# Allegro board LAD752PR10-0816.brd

Outline 338.42 x 185.75 mm; copper layers: TOP, GND1, IN1, GND2, IN2, VCC, GND3, IN3, GND4, IN4, GND5, BOTTOM. Coordinates in mm from the lower left corner of the outline.

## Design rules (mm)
net group B+: nets CPU_B+ GPU_B+
net group CLK_PCIE_6: nets CLK_PCIE_N6 CLK_PCIE_P6
net group CLK_PCIE_7: nets CLK_PCIE_N7 CLK_PCIE_P7
net group CPU_EDP_TX2P: nets CPU_EDP_TX2N CPU_EDP_TX2P
net group DDR-ALERT: nets DDR_A_ALERT# DDR_B_ALERT#
net group DDR-RST: nets DDR4_DRAMRST# H_DRAMRST#
net group DDRB-CLK: nets M_CLK_DDR2 M_CLK_DDR#2
net group DIFFPAIR29: nets FBB_CLK0 FBB_CLK0#
net group DIFFPAIR36: nets FBB_WCK3 FBB_WCK3_N
net group DIFFPAIR38: nets FBB_WCK1 FBB_WCK1_N
net group DIFFPAIR50: nets M_CLK_DDR3 M_CLK_DDR#3
net group DIFFPAIR70: nets CSSN_1 CSSP_1
net group DIFFPAIR85: nets TP_CLK TP_DATA
net group DIFFPAIR148: nets REMOTE3+ REMOTE3-
net group DIFFPAIR152: nets TBTA_I2C_SCL1_R TBTA_I2C_SDA1_R
net group DIFFPAIR156: nets CPU_DDC1CLK CPU_DDC1DATA
net group DIFFPAIR157: nets CPU_DDC2CLK CPU_DDC2DATA
net group DIFFPAIR164: nets N39112837 N39112883
net group DIFFPAIR165: nets N39112974 N39113020
net group DIFFPAIR166: nets N39113066 N39113112
net group DIFFPAIR167: nets N39113201 N39113246
net group DIFFPAIR168: nets PCIE_PTX_DRX_N13_C PCIE_PTX_DRX_P13_C
net group DIFFPAIR169: nets PCIE_PTX_DRX_N12_C PCIE_PTX_DRX_P12_C
net group DIFFPAIR170: nets PCIE_PTX_DRX_N11_C PCIE_PTX_DRX_P11_C
net group DIFFPAIR171: nets PCIE_PTX_DRX_N10_C PCIE_PTX_DRX_P10_C
net group DIFFPAIR172: nets PCIE_PTX_DRX_N9_C PCIE_PTX_DRX_P9_C
net group DIFFPAIR173: nets PCIE_PTX_DRX_N14_C PCIE_PTX_DRX_P14_C
net group DIFFPAIR174: nets PCIE_PTX_DRX_N18_C PCIE_PTX_DRX_P18_C
net group DIFFPAIR175: nets PCIE_PTX_DRX_N19_C PCIE_PTX_DRX_P19_C
net group DIFFPAIR176: nets PCIE_PTX_DRX_N20_C PCIE_PTX_DRX_P20_C
net group DIFFPAIR177: nets PCIE_PTX_DRX_N17_C PCIE_PTX_DRX_P17_C
net group DP18: nets FBA_CLK1 FBA_CLK1#
net group FBA-CLK: nets FBA_CLK0 FBA_CLK0#
net group FBB-CLK: nets FBB_CLK1 FBB_CLK1#
net group FBC-CLK: nets FBC_CLK0 FBC_CLK0#
net group FBC_CLK1: nets FBC_CLK1 FBC_CLK1#
net group FBC_WCK0: nets FBC_WCK0 FBC_WCK0_N
net group FBC_WCK2: nets FBC_WCK2 FBC_WCK2_N
net group SW_USB20_1: nets SW_USB20_N1 SW_USB20_P1
net group USB3_CRX_L_DTX_2: nets USB3_CRX_L_DTX_N2 USB3_CRX_L_DTX_P2
net group USB3_CRX_L_DTX_5: nets USB3_CRX_L_DTX_N5 USB3_CRX_L_DTX_P5
net group USB3_CTX_C_DRX_2: nets USB3_CTX_C_DRX_N2 USB3_CTX_C_DRX_P2
net group USB3_CTX_C_DRX_5: nets USB3_CTX_C_DRX_N5 USB3_CTX_C_DRX_P5
net group USB3_CTX_C_L_DRX_2: nets USB3_CTX_C_L_DRX_N2 USB3_CTX_C_L_DRX_P2
net group USB3_CTX_C_L_DRX_5: nets USB3_CTX_C_L_DRX_N5 USB3_CTX_C_L_DRX_P5
net group USB3R2: nets USB3RN2 USB3RP2
net group USB3T2: nets USB3TN2 USB3TP2
net group USB20_8_CONN: nets USB20_N8_CONN USB20_P8_CONN
net group VGA_SMB: nets VGA_SMB_CK3 VGA_SMB_DA3
net group 12: nets CFG0 CFG1 CFG2 CFG3 CFG4 CFG5 CFG6 CFG7 CFG8 CFG9 CFG10 CFG11 CFG12 CFG13 CFG14 CFG15 CFG16 CFG17 CFG18 CFG19
net group 13.5/12: nets GPU_MDP_N0 GPU_MDP_N1 GPU_MDP_N2 GPU_MDP_N3 GPU_MDP_P0 GPU_MDP_P1 GPU_MDP_P2 GPU_MDP_P3
net group 15: nets IN1_PEQ# IN2_PEQ# PEG_RCOMP
net group 25: nets EDP_RCOMP
net group ASYNCHRONOUS: nets CALDERA_RST# CDRA_RST# CPU_TRIGGER DGPU_HOLD_RST# DGPU_PEX_RST# DGPU_PWROK H_CPUPWRGD H_PECI H_PM_DOWN H_PM_SYNC_R H_PROCHOT# H_THERMTRIP# H_THERMTRIP#_R H_VCCST_PWRGD PCH_DPWROK PCH_PECI PCH_PLTRST# PCH_PWROK PCH_TRIGGER PCIECOMP PCIECOMP# PECI_KB9012 PLTRST_CPU# SYS_PWROK USB2_COMP VCCIO_PGOOD VR_HOT#
net group CODEC: nets HP2_D_L_C HP2_D_L_R HP2_D_R_C HP2_D_R_R HPOUT-L HPOUT-R
net group CRITICAL LOW SPEED: nets INTRUDER# PBTN_OUT# PCH_RTCRST# PCH_SRTCRST# PCIE_WAKE#
net group CRYSTAL: nets PCH_RTCX1 PCH_RTCX2 TBT_XTAL_25_IN TBT_XTAL_25_OUT XTAL24_IN XTAL24_OUT XTAL_OUT XTALIN XTLI XTLO
net group DDR-RCOMP: nets DDR_RCOMP0 DDR_RCOMP1 DDR_RCOMP2
net group DDRA-CLK: nets M_CLK_DDR0 M_CLK_DDR1 M_CLK_DDR#0 M_CLK_DDR#1
net group DDRA-CMD: nets DDR_A_BG0 DDR_A_BG1 DDR_A_BS0 DDR_A_BS1 DDR_A_CAS# DDR_A_MA0 DDR_A_MA1 DDR_A_MA2 DDR_A_MA3 DDR_A_MA4 DDR_A_MA5 DDR_A_MA6 DDR_A_MA7 DDR_A_MA8 DDR_A_MA9 DDR_A_MA10 DDR_A_MA11 DDR_A_MA12 DDR_A_MA13 DDR_A_RAS# DDR_A_WE#
net group DDRA-CTL: nets DDR_A_ACT# DDR_A_PAR DDR_CKE0_DIMMA DDR_CKE1_DIMMA DDR_CS0_DIMMA# DDR_CS1_DIMMA#
net group DDRA-D0: nets DDR_A_D0 DDR_A_D1 DDR_A_D2 DDR_A_D3 DDR_A_D4 DDR_A_D5 DDR_A_D6 DDR_A_D7
net group DDRA-D1: nets DDR_A_D8 DDR_A_D9 DDR_A_D10 DDR_A_D11 DDR_A_D12 DDR_A_D13 DDR_A_D14 DDR_A_D15
net group DDRA-D2: nets DDR_A_D16 DDR_A_D17 DDR_A_D18 DDR_A_D19 DDR_A_D20 DDR_A_D21 DDR_A_D22 DDR_A_D23
net group DDRA-D3: nets DDR_A_D24 DDR_A_D25 DDR_A_D26 DDR_A_D27 DDR_A_D28 DDR_A_D29 DDR_A_D30 DDR_A_D31
net group DDRA-D4: nets DDR_A_D32 DDR_A_D33 DDR_A_D34 DDR_A_D35 DDR_A_D36 DDR_A_D37 DDR_A_D38 DDR_A_D39
net group DDRA-D5: nets DDR_A_D40 DDR_A_D41 DDR_A_D42 DDR_A_D43 DDR_A_D44 DDR_A_D45 DDR_A_D46 DDR_A_D47
net group DDRA-D6: nets DDR_A_D48 DDR_A_D49 DDR_A_D50 DDR_A_D51 DDR_A_D52 DDR_A_D53 DDR_A_D54 DDR_A_D55
net group DDRA-D7: nets DDR_A_D56 DDR_A_D57 DDR_A_D58 DDR_A_D59 DDR_A_D60 DDR_A_D61 DDR_A_D62 DDR_A_D63
net group DDRA-DQS: nets DDR_A_DQS0 DDR_A_DQS1 DDR_A_DQS2 DDR_A_DQS3 DDR_A_DQS4 DDR_A_DQS5 DDR_A_DQS6 DDR_A_DQS7 DDR_A_DQS#0 DDR_A_DQS#1 DDR_A_DQS#2 DDR_A_DQS#3 DDR_A_DQS#4 DDR_A_DQS#5 DDR_A_DQS#6 DDR_A_DQS#7
net group DDRB-CMD: nets DDR_B_BG0 DDR_B_BG1 DDR_B_BS0 DDR_B_BS1 DDR_B_CAS# DDR_B_MA0 DDR_B_MA1 DDR_B_MA2 DDR_B_MA3 DDR_B_MA4 DDR_B_MA5 DDR_B_MA6 DDR_B_MA7 DDR_B_MA8 DDR_B_MA9 DDR_B_MA10 DDR_B_MA11 DDR_B_MA12 DDR_B_MA13 DDR_B_RAS# DDR_B_WE#
net group DDRB-CTL: nets DDR_B_ACT# DDR_B_PAR DDR_CKE2_DIMMB DDR_CKE3_DIMMB DDR_CS2_DIMMB# DDR_CS3_DIMMB# M_ODT0 M_ODT1 M_ODT2 M_ODT3
net group DDRB-D0: nets DDR_B_D0 DDR_B_D1 DDR_B_D2 DDR_B_D3 DDR_B_D4 DDR_B_D5 DDR_B_D6 DDR_B_D7
net group DDRB-D1: nets DDR_B_D8 DDR_B_D9 DDR_B_D10 DDR_B_D11 DDR_B_D12 DDR_B_D13 DDR_B_D14 DDR_B_D15
net group DDRB-D2: nets DDR_B_D16 DDR_B_D17 DDR_B_D18 DDR_B_D19 DDR_B_D20 DDR_B_D21 DDR_B_D22 DDR_B_D23
net group DDRB-D3: nets DDR_B_D24 DDR_B_D25 DDR_B_D26 DDR_B_D27 DDR_B_D28 DDR_B_D29 DDR_B_D30 DDR_B_D31
net group DDRB-D4: nets DDR_B_D32 DDR_B_D33 DDR_B_D34 DDR_B_D35 DDR_B_D36 DDR_B_D37 DDR_B_D38 DDR_B_D39
net group DDRB-D5: nets DDR_B_D40 DDR_B_D41 DDR_B_D42 DDR_B_D43 DDR_B_D44 DDR_B_D45 DDR_B_D46 DDR_B_D47
net group DDRB-D6: nets DDR_B_D48 DDR_B_D49 DDR_B_D50 DDR_B_D51 DDR_B_D52 DDR_B_D53 DDR_B_D54 DDR_B_D55
net group DDRB-D7: nets DDR_B_D56 DDR_B_D57 DDR_B_D58 DDR_B_D59 DDR_B_D60 DDR_B_D61 DDR_B_D62 DDR_B_D63
net group DDRB-DQS: nets DDR_B_DQS0 DDR_B_DQS1 DDR_B_DQS2 DDR_B_DQS3 DDR_B_DQS4 DDR_B_DQS5 DDR_B_DQS6 DDR_B_DQS7 DDR_B_DQS#0 DDR_B_DQS#1 DDR_B_DQS#2 DDR_B_DQS#3 DDR_B_DQS#4 DDR_B_DQS#5 DDR_B_DQS#6 DDR_B_DQS#7
net group DIFFPAIR46: nets MIC_DATA
net group DMI: nets DMI_CRX_PTX_N0 DMI_CRX_PTX_N1 DMI_CRX_PTX_N2 DMI_CRX_PTX_N3 DMI_CRX_PTX_P0 DMI_CRX_PTX_P1 DMI_CRX_PTX_P2 DMI_CRX_PTX_P3 DMI_CTX_PRX_N0 DMI_CTX_PRX_N1 DMI_CTX_PRX_N2 DMI_CTX_PRX_N3 DMI_CTX_PRX_P0 DMI_CTX_PRX_P1 DMI_CTX_PRX_P2 DMI_CTX_PRX_P3 DMIC_CLK1_R DMIC_DATA1_R
net group DP: nets CPU_DP1_AUXN CPU_DP1_AUXN_C CPU_DP1_AUXP CPU_DP1_AUXP_C CPU_DP1_N0 CPU_DP1_N0_C CPU_DP1_N1 CPU_DP1_N1_C CPU_DP1_N2 CPU_DP1_N2_C CPU_DP1_N3 CPU_DP1_N3_C CPU_DP1_P0 CPU_DP1_P0_C CPU_DP1_P1 CPU_DP1_P1_C CPU_DP1_P2 CPU_DP1_P2_C CPU_DP1_P3 CPU_DP1_P3_C CPU_DP2_AUXN CPU_DP2_AUXN_C CPU_DP2_AUXP CPU_DP2_AUXP_C CPU_DP2_N0 CPU_DP2_N0_C CPU_DP2_N1 CPU_DP2_N1_C CPU_DP2_N2 CPU_DP2_N2_C CPU_DP2_N3 CPU_DP2_N3_C CPU_DP2_P0 CPU_DP2_P0_C CPU_DP2_P1 CPU_DP2_P1_C CPU_DP2_P2 CPU_DP2_P2_C CPU_DP2_P3 CPU_DP2_P3_C
net group EDP-CPU: nets CPU_EDP_AUX CPU_EDP_AUX# CPU_EDP_AUX#_C CPU_EDP_AUX_C CPU_EDP_N0_C CPU_EDP_N1_C CPU_EDP_N2_C CPU_EDP_N3_C CPU_EDP_P0_C CPU_EDP_P1_C CPU_EDP_P2_C CPU_EDP_P3_C CPU_EDP_TX0N CPU_EDP_TX0P CPU_EDP_TX1N CPU_EDP_TX1P CPU_EDP_TX3N CPU_EDP_TX3P
net group EDP-GPU: nets GPU_AUXN/DDC_C GPU_AUXP/DDC_C GPU_TX0N_C GPU_TX0P_C GPU_TX1N_C GPU_TX1P_C GPU_TX2N_C GPU_TX2P_C GPU_TX3N_C GPU_TX3P_C
net group EDP-MUX: nets EDP_AUX#_C EDP_AUX_C EDP_TX0#_C EDP_TX0_C EDP_TX1#_C EDP_TX1_C EDP_TX2#_C EDP_TX2_C EDP_TX3#_C EDP_TX3_C MUX_EDP_A0N MUX_EDP_A0P MUX_EDP_A1N MUX_EDP_A1P MUX_EDP_A2N MUX_EDP_A2P MUX_EDP_A3N MUX_EDP_A3P MUX_EDP_AUXN MUX_EDP_AUXP
net group EMC: nets BOOT_1.2V BST_1.2V BST_3V BST_5V CPU_XDP_TRST# MIC_CLK RJ45_CT0 RJ45_CT1 RJ45_CT2 RJ45_CT3 SPI_MOCLK TBT_EE_CLK TBT_TCK
net group FBA-CMD: nets FBA_ABI#_H FBA_ABI#_L FBA_CAS#_H FBA_CAS#_L FBA_CKE_H FBA_CKE_L FBA_CS#_H FBA_CS#_L FBA_MA0_H FBA_MA0_L FBA_MA1_H FBA_MA1_L FBA_MA2_H FBA_MA2_L FBA_MA3_H FBA_MA3_L FBA_MA4_H FBA_MA4_L FBA_MA5_H FBA_MA5_L FBA_MA6_H FBA_MA6_L FBA_MA7_H FBA_MA7_L FBA_MA8_H FBA_MA8_L FBA_RAS#_H FBA_RAS#_L FBA_WE#_H FBA_WE#_L
net group FBA-D0: nets FBA_D0 FBA_D1 FBA_D2 FBA_D3 FBA_D4 FBA_D5 FBA_D6 FBA_D7
net group FBA-D1: nets FBA_D8 FBA_D9 FBA_D10 FBA_D11 FBA_D12 FBA_D13 FBA_D14 FBA_D15
net group FBA-D2: nets FBA_D16 FBA_D17 FBA_D18 FBA_D19 FBA_D20 FBA_D21 FBA_D22 FBA_D23
net group FBA-D3: nets FBA_D24 FBA_D25 FBA_D26 FBA_D27 FBA_D28 FBA_D29 FBA_D30 FBA_D31
net group FBA-D4: nets FBA_D32 FBA_D33 FBA_D34 FBA_D35 FBA_D36 FBA_D37 FBA_D38 FBA_D39
net group FBA-D5: nets FBA_D40 FBA_D41 FBA_D42 FBA_D43 FBA_D44 FBA_D45 FBA_D46 FBA_D47
net group FBA-D6: nets FBA_D48 FBA_D49 FBA_D50 FBA_D51 FBA_D52 FBA_D53 FBA_D54 FBA_D55
net group FBA-D7: nets FBA_D56 FBA_D57 FBA_D58 FBA_D59 FBA_D60 FBA_D61 FBA_D62 FBA_D63
net group FBA-DBI: nets FBA_DBI0# FBA_DBI1# FBA_DBI2# FBA_DBI3# FBA_DBI4# FBA_DBI5# FBA_DBI6# FBA_DBI7#
net group FBA-EDC: nets FBA_EDC0 FBA_EDC1 FBA_EDC2 FBA_EDC3 FBA_EDC4 FBA_EDC5 FBA_EDC6 FBA_EDC7
net group FBA-WCK: nets FBA_WCK0 FBA_WCK0_N FBA_WCK1 FBA_WCK1_N FBA_WCK2 FBA_WCK2_N FBA_WCK3 FBA_WCK3_N
net group FBB-CMD: nets FBB_ABI#_H FBB_ABI#_L FBB_CAS#_H FBB_CAS#_L FBB_CKE_H FBB_CKE_L FBB_CS#_H FBB_CS#_L FBB_MA0_H FBB_MA0_L FBB_MA1_H FBB_MA1_L FBB_MA2_H FBB_MA2_L FBB_MA3_H FBB_MA3_L FBB_MA4_H FBB_MA4_L FBB_MA5_H FBB_MA5_L FBB_MA6_H FBB_MA6_L FBB_MA7_H FBB_MA7_L FBB_MA8_H FBB_MA8_L FBB_RAS#_H FBB_RAS#_L FBB_WE#_H FBB_WE#_L
net group FBB-D0: nets FBB_D0 FBB_D1 FBB_D2 FBB_D3 FBB_D4 FBB_D5 FBB_D6 FBB_D7
net group FBB-D1: nets FBB_D8 FBB_D9 FBB_D10 FBB_D11 FBB_D12 FBB_D13 FBB_D14 FBB_D15
net group FBB-D2: nets FBB_D16 FBB_D17 FBB_D18 FBB_D19 FBB_D20 FBB_D21 FBB_D22 FBB_D23
net group FBB-D3: nets FBB_D24 FBB_D25 FBB_D26 FBB_D27 FBB_D28 FBB_D29 FBB_D30 FBB_D31
net group FBB-D4: nets FBB_D32 FBB_D33 FBB_D34 FBB_D35 FBB_D36 FBB_D37 FBB_D38 FBB_D39
net group FBB-D5: nets FBB_D40 FBB_D41 FBB_D42 FBB_D43 FBB_D44 FBB_D45 FBB_D46 FBB_D47
net group FBB-D6: nets FBB_D48 FBB_D49 FBB_D50 FBB_D51 FBB_D52 FBB_D53 FBB_D54 FBB_D55
net group FBB-D7: nets FBB_D56 FBB_D57 FBB_D58 FBB_D59 FBB_D60 FBB_D61 FBB_D62 FBB_D63
net group FBB-DBI: nets FBB_DBI0# FBB_DBI1# FBB_DBI2# FBB_DBI3# FBB_DBI4# FBB_DBI5# FBB_DBI6# FBB_DBI7#
net group FBB-EDC: nets FBB_EDC0 FBB_EDC1 FBB_EDC2 FBB_EDC3 FBB_EDC4 FBB_EDC5 FBB_EDC6 FBB_EDC7
net group FBB-WCK: nets FBB_WCK0 FBB_WCK0_N FBB_WCK2 FBB_WCK2_N
net group FBC-CMD: nets FBC_ABI#_H FBC_ABI#_L FBC_CAS#_H FBC_CAS#_L FBC_CKE_H FBC_CKE_L FBC_CS#_H FBC_CS#_L FBC_MA0_H FBC_MA0_L FBC_MA1_H FBC_MA1_L FBC_MA2_H FBC_MA2_L FBC_MA3_H FBC_MA3_L FBC_MA4_H FBC_MA4_L FBC_MA5_H FBC_MA5_L FBC_MA6_H FBC_MA6_L FBC_MA7_H FBC_MA7_L FBC_MA8_H FBC_MA8_L FBC_RAS#_H FBC_RAS#_L FBC_WE#_H FBC_WE#_L
net group FBC-D0: nets FBC_D0 FBC_D1 FBC_D2 FBC_D3 FBC_D4 FBC_D5 FBC_D6 FBC_D7
net group FBC-D1: nets FBC_D8 FBC_D9 FBC_D10 FBC_D11 FBC_D12 FBC_D13 FBC_D14 FBC_D15
net group FBC-D2: nets FBC_D16 FBC_D17 FBC_D18 FBC_D19 FBC_D20 FBC_D21 FBC_D22 FBC_D23
net group FBC-D3: nets FBC_D24 FBC_D25 FBC_D26 FBC_D27 FBC_D28 FBC_D29 FBC_D30 FBC_D31
net group FBC-D4: nets FBC_D32 FBC_D33 FBC_D34 FBC_D35 FBC_D36 FBC_D37 FBC_D38 FBC_D39
net group FBC-D5: nets FBC_D40 FBC_D41 FBC_D42 FBC_D43 FBC_D44 FBC_D45 FBC_D46 FBC_D47
net group FBC-D6: nets FBC_D48 FBC_D49 FBC_D50 FBC_D51 FBC_D52 FBC_D53 FBC_D54 FBC_D55
net group FBC-D7: nets FBC_D56 FBC_D57 FBC_D58 FBC_D59 FBC_D60 FBC_D61 FBC_D62 FBC_D63
net group FBC-DBI: nets FBC_DBI0# FBC_DBI1# FBC_DBI2# FBC_DBI3# FBC_DBI4# FBC_DBI5# FBC_DBI6# FBC_DBI7#
net group FBC-EDC: nets FBC_EDC0 FBC_EDC1 FBC_EDC2 FBC_EDC3 FBC_EDC4 FBC_EDC5 FBC_EDC6 FBC_EDC7
net group FBC-WCK: nets FBC_WCK1 FBC_WCK1_N FBC_WCK3 FBC_WCK3_N
net group FBD-CLK: nets FBD_CLK0 FBD_CLK0# FBD_CLK1 FBD_CLK1#
net group FBD-CMD: nets FBD_ABI#_H FBD_ABI#_L FBD_CAS#_H FBD_CAS#_L FBD_CKE_H FBD_CKE_L FBD_CS#_H FBD_CS#_L FBD_MA0_H FBD_MA0_L FBD_MA1_H FBD_MA1_L FBD_MA2_H FBD_MA2_L FBD_MA3_H FBD_MA3_L FBD_MA4_H FBD_MA4_L FBD_MA5_H FBD_MA5_L FBD_MA6_H FBD_MA6_L FBD_MA7_H FBD_MA7_L FBD_MA8_H FBD_MA8_L FBD_RAS#_H FBD_RAS#_L FBD_WE#_H FBD_WE#_L
net group FBD-D0: nets FBD_D0 FBD_D1 FBD_D2 FBD_D3 FBD_D4 FBD_D5 FBD_D6 FBD_D7
net group FBD-D1: nets FBD_D8 FBD_D9 FBD_D10 FBD_D11 FBD_D12 FBD_D13 FBD_D14 FBD_D15
net group FBD-D2: nets FBD_D16 FBD_D17 FBD_D18 FBD_D19 FBD_D20 FBD_D21 FBD_D22 FBD_D23
net group FBD-D3: nets FBD_D24 FBD_D25 FBD_D26 FBD_D27 FBD_D28 FBD_D29 FBD_D30 FBD_D31
net group FBD-D4: nets FBD_D32 FBD_D33 FBD_D34 FBD_D35 FBD_D36 FBD_D37 FBD_D38 FBD_D39
net group FBD-D5: nets FBD_D40 FBD_D41 FBD_D42 FBD_D43 FBD_D44 FBD_D45 FBD_D46 FBD_D47
net group FBD-D6: nets FBD_D48 FBD_D49 FBD_D50 FBD_D51 FBD_D52 FBD_D53 FBD_D54 FBD_D55
net group FBD-D7: nets FBD_D56 FBD_D57 FBD_D58 FBD_D59 FBD_D60 FBD_D61 FBD_D62 FBD_D63
net group FBD-DBI: nets FBD_DBI0# FBD_DBI1# FBD_DBI2# FBD_DBI3# FBD_DBI4# FBD_DBI5# FBD_DBI6# FBD_DBI7#
net group FBD-EDC: nets FBD_EDC0 FBD_EDC1 FBD_EDC2 FBD_EDC3 FBD_EDC4 FBD_EDC5 FBD_EDC6 FBD_EDC7
net group FBD-WCK: nets FBD_WCK0 FBD_WCK0_N FBD_WCK1 FBD_WCK1_N FBD_WCK2 FBD_WCK2_N FBD_WCK3 FBD_WCK3_N
net group HDA: nets HDA_SPKR ME_EN PCH_AZ_BITCLK PCH_AZ_CODEC_BITCLK PCH_AZ_CODEC_RST# PCH_AZ_CODEC_RST#_R PCH_AZ_CODEC_SDIN0 PCH_AZ_CODEC_SDOUT PCH_AZ_CODEC_SYNC PCH_AZ_RST# PCH_AZ_SDOUT PCH_AZ_SYNC
net group I2C: nets I2C_CLK I2C_DAT TBT_I2C_SCL TBT_I2C_SDA TBTA_I2C_INT TBTB_I2C_INT
net group LAN: nets LAN_MDIN0 LAN_MDIN1 LAN_MDIN2 LAN_MDIN3 LAN_MDIP0 LAN_MDIP1 LAN_MDIP2 LAN_MDIP3
net group LAN(NO_REF): nets RJ45_MDI0+ RJ45_MDI0- RJ45_MDI1+ RJ45_MDI1- RJ45_MDI2+ RJ45_MDI2- RJ45_MDI3+ RJ45_MDI3-
net group LPC: nets LPC_AD0 LPC_AD1 LPC_AD2 LPC_AD3 LPC_FRAME#
net group MDP: nets DISP_CLK_AUXP_CONN
net group PCIE: nets PCIE_PRX_DTX_N5 PCIE_PRX_DTX_N5_C PCIE_PRX_DTX_N6 PCIE_PRX_DTX_N9 PCIE_PRX_DTX_N10 PCIE_PRX_DTX_N11 PCIE_PRX_DTX_N12 PCIE_PRX_DTX_N13 PCIE_PRX_DTX_N14 PCIE_PRX_DTX_N17 PCIE_PRX_DTX_N18 PCIE_PRX_DTX_N19 PCIE_PRX_DTX_N20 PCIE_PRX_DTX_P5 PCIE_PRX_DTX_P5_C PCIE_PRX_DTX_P6 PCIE_PRX_DTX_P9 PCIE_PRX_DTX_P10 PCIE_PRX_DTX_P11 PCIE_PRX_DTX_P12 PCIE_PRX_DTX_P13 PCIE_PRX_DTX_P14 PCIE_PRX_DTX_P17 PCIE_PRX_DTX_P18 PCIE_PRX_DTX_P19 PCIE_PRX_DTX_P20 PCIE_PTX_DRX_N5 PCIE_PTX_DRX_N5_C PCIE_PTX_DRX_N6 PCIE_PTX_DRX_N6_C PCIE_PTX_DRX_N9 PCIE_PTX_DRX_N10 PCIE_PTX_DRX_N11 PCIE_PTX_DRX_N12 PCIE_PTX_DRX_N13 PCIE_PTX_DRX_N14 PCIE_PTX_DRX_N17 PCIE_PTX_DRX_N18 PCIE_PTX_DRX_N19 PCIE_PTX_DRX_N20 PCIE_PTX_DRX_P5 PCIE_PTX_DRX_P5_C PCIE_PTX_DRX_P6 PCIE_PTX_DRX_P6_C PCIE_PTX_DRX_P9 PCIE_PTX_DRX_P10 PCIE_PTX_DRX_P11 PCIE_PTX_DRX_P12 PCIE_PTX_DRX_P13 PCIE_PTX_DRX_P14 PCIE_PTX_DRX_P17 PCIE_PTX_DRX_P18 PCIE_PTX_DRX_P19 PCIE_PTX_DRX_P20
net group PEG: nets CRX_N8 CRX_N9 CRX_N10 CRX_N11 CRX_P8 CRX_P9 CRX_P10 CRX_P11 PEG_CRX_C_GTX_N8 PEG_CRX_C_GTX_N9 PEG_CRX_C_GTX_N10 PEG_CRX_C_GTX_N11 PEG_CRX_C_GTX_P8 PEG_CRX_C_GTX_P9 PEG_CRX_C_GTX_P10 PEG_CRX_C_GTX_P11 PEG_CRX_GTX_N0 PEG_CRX_GTX_N0_C PEG_CRX_GTX_N1 PEG_CRX_GTX_N1_C PEG_CRX_GTX_N2 PEG_CRX_GTX_N2_C PEG_CRX_GTX_N3 PEG_CRX_GTX_N3_C PEG_CRX_GTX_N4 PEG_CRX_GTX_N4_C PEG_CRX_GTX_N5 PEG_CRX_GTX_N5_C PEG_CRX_GTX_N6 PEG_CRX_GTX_N6_C PEG_CRX_GTX_N7 PEG_CRX_GTX_N7_C PEG_CRX_GTX_N8 PEG_CRX_GTX_N9 PEG_CRX_GTX_N10 PEG_CRX_GTX_N11 PEG_CRX_GTX_P0 PEG_CRX_GTX_P0_C PEG_CRX_GTX_P1 PEG_CRX_GTX_P1_C PEG_CRX_GTX_P2 PEG_CRX_GTX_P2_C PEG_CRX_GTX_P3 PEG_CRX_GTX_P3_C PEG_CRX_GTX_P4 PEG_CRX_GTX_P4_C PEG_CRX_GTX_P5 PEG_CRX_GTX_P5_C PEG_CRX_GTX_P6 PEG_CRX_GTX_P6_C PEG_CRX_GTX_P7 PEG_CRX_GTX_P7_C PEG_CRX_GTX_P8 PEG_CRX_GTX_P9 PEG_CRX_GTX_P10 PEG_CRX_GTX_P11 PEG_CRX_TTX_N12 PEG_CRX_TTX_N12_C PEG_CRX_TTX_N13 PEG_CRX_TTX_N13_C PEG_CRX_TTX_N14 PEG_CRX_TTX_N14_C PEG_CRX_TTX_N15 PEG_CRX_TTX_N15_C PEG_CRX_TTX_P12 PEG_CRX_TTX_P12_C PEG_CRX_TTX_P13 PEG_CRX_TTX_P13_C PEG_CRX_TTX_P14 PEG_CRX_TTX_P14_C PEG_CRX_TTX_P15 PEG_CRX_TTX_P15_C PEG_CTX_C_GRX_N0 PEG_CTX_C_GRX_N1 PEG_CTX_C_GRX_N2 PEG_CTX_C_GRX_N3 PEG_CTX_C_GRX_N4 PEG_CTX_C_GRX_N5 PEG_CTX_C_GRX_N6 PEG_CTX_C_GRX_N7 PEG_CTX_C_GRX_N8 PEG_CTX_C_GRX_N9 PEG_CTX_C_GRX_N10 PEG_CTX_C_GRX_N11 PEG_CTX_C_GRX_P0 PEG_CTX_C_GRX_P1 PEG_CTX_C_GRX_P2 PEG_CTX_C_GRX_P3 PEG_CTX_C_GRX_P4 PEG_CTX_C_GRX_P5 PEG_CTX_C_GRX_P6 PEG_CTX_C_GRX_P7 PEG_CTX_C_GRX_P8 PEG_CTX_C_GRX_P9 PEG_CTX_C_GRX_P10 PEG_CTX_C_GRX_P11 PEG_CTX_GRX_N0 PEG_CTX_GRX_N1 PEG_CTX_GRX_N2 PEG_CTX_GRX_N3 PEG_CTX_GRX_N4 PEG_CTX_GRX_N5 PEG_CTX_GRX_N6 PEG_CTX_GRX_N7 PEG_CTX_GRX_N8 PEG_CTX_GRX_N9 PEG_CTX_GRX_N10 PEG_CTX_GRX_N11 PEG_CTX_GRX_P0 PEG_CTX_GRX_P1 PEG_CTX_GRX_P2 PEG_CTX_GRX_P3 PEG_CTX_GRX_P4 PEG_CTX_GRX_P5 PEG_CTX_GRX_P6 PEG_CTX_GRX_P7 PEG_CTX_GRX_P8 PEG_CTX_GRX_P9 PEG_CTX_GRX_P10 PEG_CTX_GRX_P11 PEG_CTX_TRX_N12 PEG_CTX_TRX_N12_C PEG_CTX_TRX_N13 PEG_CTX_TRX_N13_C PEG_CTX_TRX_N14 PEG_CTX_TRX_N14_C PEG_CTX_TRX_N15 PEG_CTX_TRX_N15_C PEG_CTX_TRX_P12 PEG_CTX_TRX_P12_C PEG_CTX_TRX_P13 PEG_CTX_TRX_P13_C PEG_CTX_TRX_P14 PEG_CTX_TRX_P14_C PEG_CTX_TRX_P15 PEG_CTX_TRX_P15_C
net group PLATFORM-CLK: nets CLK_PCI_LPC CLK_PCIE_DGPU#_C CLK_PCIE_DGPU_C CLK_PCIE_N1 CLK_PCIE_N2 CLK_PCIE_N3 CLK_PCIE_N4 CLK_PCIE_N5 CLK_PCIE_P1 CLK_PCIE_P2 CLK_PCIE_P3 CLK_PCIE_P4 CLK_PCIE_P5 CLK_PEG_GPU CLK_PEG_GPU# CPU_24MHZ_N CPU_24MHZ_P PCH_CPU_BCLK_N PCH_CPU_BCLK_P PCH_CPU_PCIBCLK_N PCH_CPU_PCIBCLK_P PCH_XDP_CLK_N PCH_XDP_CLK_P
net group POWER: nets +0.6VS +0.6VSP +0.9V_CIO +0.9V_DP +0.9V_LVR_OUT +0.9V_PCIE +0.9V_SVR +0.9V_USB +1.2V_DDR +1.2V_VCCPLL_OC +1.2VP +1.8VA_TBTA_LDO +1.8VD_TBTA_LDO +1.8VS +1V_MPHY +1V_PCH +1V_PCH_PRIM +1V_VCCDSW +1VALWP +1VALWP_B+ +1VALWP_PGOOD +2.5V_MEM +2.5V_MEMP +2.5VOUT +2.5VSP_ON +2.5VSP_VIN +3.3V_1.8V_DVDD +3.3V_1.8V_DVDD_IO +3.3V_ANA_PCIE +3.3V_ANA_USB2 +3.3V_F383 +3.3V_FLASH +3.3V_LC +3.3V_TBT_SX +3.3V_TBT_SX_R +3V_PCH +3VALW_PD +3VALWP +3VGS +3VLP +3VS_CAM +3VS_DP +3VS_TBT +3VS_TOUCH +5V_PVDD +5V_TOBII +5V_USB_PWR1 +5V_USB_PWR2 +5V_USBC_VBUS +5VA +5VALW_LED +5VALWP +5VS_TP_LED +AVDDH +AVDDL +CODEC_AVDD2 +DVDDL +EC_VCCA +HDMI_5V_OUT +INV_PWR_SRC +LAN_IO +LCDVDD +PVDD +RBIAS +RTC_CELL +V18R +VCCIOP +VCCST +VCCSTG +VDD_TOUCH +VDDCT_L +VGA_PCIE +VGA_PCIEP
net group PS8409-HDMI: nets TMDS_C_TX0N TMDS_C_TX0P TMDS_C_TX1N TMDS_C_TX1P TMDS_C_TX2N TMDS_C_TX2P TMDS_C_TXCN TMDS_C_TXCP TMDS_R_TX0N TMDS_R_TX0P TMDS_R_TX1N TMDS_R_TX1P TMDS_R_TX2N TMDS_R_TX2P TMDS_R_TXCN TMDS_R_TXCP
net group SATA: nets SATA_PRX_DTX_N3 SATA_PRX_DTX_P3 SATA_PTX_DRX_N3 SATA_PTX_DRX_P3
net group SENSE: nets VCCGT_SENSE VCCIO_SENSE VCCSA_SENSE VCCSENSE VSSGT_SENSE VSSIO_SENSE VSSSA_SENSE VSSSENSE
net group SMBUS: nets CLK_SMB DAT_SMB EC_SMB_CK1 EC_SMB_CK2 EC_SMB_DA1 EC_SMB_DA2 PCH_SMBCLK PCH_SMBDATA SML0CLK SML0DATA SML1CLK SML1DATA
net group SPI: nets PCH_SPI_CLK PCH_SPI_CLK_R PCH_SPI_CS# PCH_SPI_HOLD# PCH_SPI_HOLD#_R PCH_SPI_SI PCH_SPI_SI_R PCH_SPI_SO PCH_SPI_SO_R PCH_SPI_WP# PCH_SPI_WP#_R PCH_SYS_PWROK_XDP
net group SVID: nets VR_SVID_ALERT# VR_SVID_CLK VR_SVID_DATA
net group TBT: nets TBT_A_AUX_N TBT_A_AUX_N_C TBT_A_AUX_P TBT_A_AUX_P_C TBTA_DIG_AUD_N TBTA_DIG_AUD_P TBTA_LSRX TBTA_LSTX TBTA_SBU1 TBTA_SBU2 USB3_A_TRX_DTX_N0 USB3_A_TRX_DTX_N1 USB3_A_TRX_DTX_P0 USB3_A_TRX_DTX_P1 USB3_A_TTX_C_DRX_N0 USB3_A_TTX_C_DRX_N1 USB3_A_TTX_C_DRX_P0 USB3_A_TTX_C_DRX_P1 USB3_A_TTX_DRX_N0 USB3_A_TTX_DRX_N1 USB3_A_TTX_DRX_P0 USB3_A_TTX_DRX_P1
net group THERMAL: nets REMOTE1+ REMOTE1- REMOTE2+ REMOTE2-
net group TMDS-EDP: nets GPU_AUXN/DDC GPU_AUXP/DDC GPU_TX0N GPU_TX0P GPU_TX1N GPU_TX1P GPU_TX2N GPU_TX2P GPU_TX3N GPU_TX3P
net group TMDS-HDMI: nets HDMI_CTRLCLK HDMI_CTRLDAT TMDS_TX0N TMDS_TX0P TMDS_TX1N TMDS_TX1P TMDS_TX2N TMDS_TX2P TMDS_TXCN TMDS_TXCP
net group TMDS-MDP: nets DISP_DAT_AUXN_CONN DP_AUXN_C DP_AUXP_C GPU_DPC_AUX GPU_DPC_AUX# MDP_AUX#_SDA MDP_AUX_SCL MDP_LANE_N0_C MDP_LANE_N1_C MDP_LANE_N2_C MDP_LANE_N3_C MDP_LANE_P0_C MDP_LANE_P1_C MDP_LANE_P2_C MDP_LANE_P3_C
net group USB20: nets TBT_A_USB20_L_NB TBT_A_USB20_L_NT TBT_A_USB20_L_PB TBT_A_USB20_L_PT TBT_A_USB20_N TBT_A_USB20_NB TBT_A_USB20_NT TBT_A_USB20_P TBT_A_USB20_PB TBT_A_USB20_PT USB20_CAM_N7_R USB20_CAM_P7_R USB20_N1 USB20_N1_CONN USB20_N2 USB20_N3 USB20_N3_CONN USB20_N4 USB20_N5 USB20_N6 USB20_N7 USB20_N8 USB20_N9 USB20_N9_L USB20_P1 USB20_P1_CONN USB20_P2 USB20_P3 USB20_P3_CONN USB20_P4 USB20_P5 USB20_P6 USB20_P7 USB20_P8 USB20_P9 USB20_P9_L
net group USB30: nets USB3_CRX_L_DTX_N1 USB3_CRX_L_DTX_P1 USB3_CTX_C_DRX_N1 USB3_CTX_C_DRX_P1 USB3_CTX_C_L_DRX_N1 USB3_CTX_C_L_DRX_P1 USB3RN1 USB3RN3 USB3RN3_C USB3RN4 USB3RN5 USB3RP1 USB3RP3 USB3RP3_C USB3RP4 USB3RP5 USB3TN1 USB3TN3 USB3TN4 USB3TN5 USB3TP1 USB3TP3 USB3TP4 USB3TP5
net group VREF: nets +V_DDR_REFA +V_DDR_REFA_R +V_DDR_REFB +V_DDR_REFB_R
net group XDP: nets XDP_PRDY# XDP_PREQ# XDP_TMS
nets with their own width: min track width 0.254; nets ECAGND
nets with their own width: min track width 0.381; nets +VDD_MEM15_REFDB
nets with their own width: min track width 0.508; nets +1VALW +3VALW +3VS +5VALW +5VS +VCC_CORE +VCCGT +VCCIO +VCCSA +VDDCI +VGA_CORE ALIEN_LED_B_DRV# ALIEN_LED_G_DRV# ALIEN_LED_R_DRV# B+ BATT_CHG_LED BATT_CHG_LED# BATT_LOW_LED BATT_LOW_LED# EN_TPLED GND GNDA LAN_LED2# LAN_LED2#_R LOGO_LED_B_DRV# LOGO_LED_G_DRV# LOGO_LED_R_DRV# POWER_LED PWR_B_7313# PWR_G_7313# PWR_LED# PWR_R_7313# TP_LED_B# TP_LED_EN TP_LED_G# TP_LED_R#
nets with their own width: min track width 1.016; nets ISENSEP_L ISENSEP_L_R ISENSEP_R ISENSEP_R_R IVSENSE_L IVSENSE_R LINE1_L LINE1_R RJ45_CT VSENSEN_L VSENSEN_R
nets with their own width: min track width 1.524; nets +5V_HDD B+_BIAS
nets with their own width: min track width 2.032; nets +3VS_SSD
nets with their own width: min track width 3.048; nets +TBTA_VBUS

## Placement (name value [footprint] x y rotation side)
C2  0.1U_0402_10V6K  [C_0402]  192.4 14.51 0 bottom
C3  2200P_0402_25V7K  [C_0402]  128.04 101.48 180 bottom
C4  1U_0402_6.3V6K  [C_0402]  176.73 77.29 180 top
C6  0.1U_0402_10V7K  [C_0402]  178.17 82.37 0 top
C7  1U_0402_6.3V6K  [C_0402]  182.48 77.04 0 top
C10  0.1U_0402_10V7K  [C_0402]  181.02 82.37 0 top
C11  0.1U_0402_10V7K  [C_0402]  130 102.15 270 bottom
C29  0.1U_0402_16V4Z  [C_0402]  193.25 12.92 180 top
C256  10U_0402_6.3V6M  [C_0402]  58.09 9.66 180 bottom
C257  10U_0603_6.3V6M  [C_0603]  58.29 10.73 180 bottom
C258  0.1U_0402_16V7K  [C_0402]  65.39 16.92 90 bottom
C260  10U_0402_6.3V6M  [C_0402]  72.13 11.67 0 bottom
C261  10U_0603_6.3V6M  [C_0603]  71.6 10.61 0 bottom
C262  10U_0603_6.3V6M  [C_0603]  67.61 17.21 0 bottom
C263  0.1U_0402_10V7K  [C_0402]  67.98 18.27 0 bottom
C264  10U_0603_6.3V6M  [C_0603]  59.93 16.21 180 bottom
C265  0.1U_0402_10V7K  [C_0402]  59.76 17.28 180 bottom
C266  10U_0402_6.3V6M  [C_0402]  203.98 60.27 180 top
C267  10U_0603_6.3V6M  [C_0603]  203.98 59 180 top
C268  0.01U_0402_16V  [C_0402]  197.96 64.52 180 top
C269  10U_0603_6.3V6M  [C_0603]  197.75 62.07 270 top
C270  0.1U_0402_10V7K  [C_0402]  196.48 62.07 270 top
C617  33P_0402_50V8J  [C_0402]  333.78 47.2 180 top
C618  33P_0402_50V8J  [C_0402]  333.78 46.31 180 top
C620  33P_0402_50V8J  [C_0402]  275.1 23.21 180 top
C621  0.047U_0402_16V4Z  [C_0402]  331.55 30.38 180 top
C622  22U_0402_6.3V6M  [C_0402]  333.38 48.33 90 top
C623  0.047U_0402_16V4Z  [C_0402]  331.55 31.26 180 top
C624  22U_0402_6.3V6M  [C_0402]  275.1 19.53 180 top
C625  0.047U_0402_16V4Z  [C_0402]  275.1 20.42 180 top
C627  0.047U_0402_16V4Z  [C_0402]  275.1 22.26 180 top
C628  33P_0402_50V8J  [C_0402]  275.1 21.3 180 top
C629  33P_0402_50V8J  [C_0402]  250.01 5.95 270 top
C630  33P_0402_50V8J  [C_0402]  253.82 5.95 270 top
C631  150U_B15G_6.3VM_R70M  [C_B15G]  262.76 18.99 0 bottom
C632  0.047U_0402_16V4Z  [C_0402]  252.87 5.95 270 top
C633  22U_0402_6.3V6M  [C_0402]  237.69 5.94 270 top
C634  0.047U_0402_16V4Z  [C_0402]  250.96 5.95 270 top
C635  22U_0402_6.3V6M  [C_0402]  334.34 48.34 90 top
C636  22U_0402_6.3V6M  [C_0402]  333.88 30.39 0 top
C637  22U_0402_6.3V6M  [C_0402]  279.87 7.53 180 top
C638  22U_0402_6.3V6M  [C_0402]  279.87 6.57 180 top
C639  22U_0402_6.3V6M  [C_0402]  235.91 5.95 270 top
C640  22U_0402_6.3V6M  [C_0402]  236.8 5.95 270 top
C1240  47U_0805_6.3V6M  [C_0805]  259.61 19.54 135 bottom
C1241  47U_0805_6.3V6M  [C_0805]  260.85 20.77 135 bottom
C1242  47U_0805_6.3V6M  [C_0805]  258.37 18.3 135 bottom
C2498  0.1U_0402_10V6K  [C_0402]  184.8 53.44 90 bottom
C2499  0.1U_0402_10V6K  [C_0402]  204.06 107.18 270 bottom
C2500  2200P_0402_25V7K  [C_0402]  141.69 128.43 180 bottom
C2502  2200P_0402_25V7K  [C_0402]  185.69 54.52 90 bottom
C2503  2200P_0402_25V7K  [C_0402]  205.85 108.96 180 bottom
C2504  2200P_0402_25V7K  [C_0402]  187.54 53.58 180 bottom
C2505  2200P_0402_25V7K  [C_0402]  277.39 69.88 180 top
C2506  220P_0402_50V8J  [C_0402]  64.31 11.84 270 bottom
C2507  470P_0402_50V7K  [C_0402]  65.2 11.84 270 bottom
C2508  1U_0402_6.3V  [C_0402]  191.08 15.02 90 top
C2509  0.1U_0402_25V6K~D  [C_0402]  192.99 18.26 180 top
C2510  2200P_0402_25V7K  [C_0402]  188.48 49.98 270 bottom
C2511  2200P_0402_25V7K  [C_0402]  286 36.21 0 bottom
C2512  10U_0603_6.3V6M  [C_0603]  315.79 49.31 180 top
C2513  10U_0603_6.3V6M  [C_0603]  315.79 47.97 180 top
C2514  10U_0603_6.3V6M  [C_0603]  318.27 55.21 0 top
C2515  10U_0603_6.3V6M  [C_0603]  318.27 56.48 0 top
C2516  0.1U_0402_10V7K  [C_0402]  316.43 55.12 0 top
C2518  0.1U_0402_10V7K  [C_0402]  129.03 97.71 90 top
C2519  0.1U_0402_10V7K  [C_0402]  126.63 97.86 90 bottom
C2520  0.1U_0402_10V7K  [C_0402]  184.26 77.86 270 top
C2521  0.1U_0402_10V7K  [C_0402]  177.67 77.38 270 top
C2522  0.1U_0402_10V7K  [C_0402]  201.6 60.94 270 top
C2523  0.1U_0402_10V7K  [C_0402]  63.42 11.84 270 bottom
C2524  0.1U_0402_10V7K  [C_0402]  66.07 11.84 270 bottom
C2525  0.1U_0402_10V7K  [C_0402]  61.62 17.58 180 bottom
CA1  4.7U_0402_6.3V6M  [C_0402]  33.85 24.03 0 bottom
CA2  0.1U_0402_16V7K  [C_0402]  33.85 24.92 0 bottom
CA3  10U_0603_6.3V6M  [C_0603]  30.56 36.79 0 bottom
CA4  0.1U_0402_16V7K  [C_0402]  30.81 35.71 0 bottom
CA5  10U_0603_6.3V6M  [C_0603]  27.38 40.55 90 bottom
CA6  0.1U_0402_16V7K  [C_0402]  27.81 39.59 0 bottom
CA7  10U_0603_6.3V6M  [C_0603]  33.36 36.79 180 top
CA8  0.1U_0402_16V7K  [C_0402]  33.12 35.71 180 top
CA9  10U_0603_6.3V6M  [C_0603]  33.36 38 180 top
CA10  0.1U_0402_16V7K  [C_0402]  33.12 39.08 180 top
CA11  10P_0402_50V8J  [C_0402]  38.5 27.85 180 top
CA12  0.1U_0402_16V7K  [C_0402]  37.49 30.56 90 bottom
CA13  4.7U_0402_6.3V6M  [C_0402]  38.38 30.56 90 bottom
CA14  10U_0603_6.3V6M  [C_0603]  29.17 36.54 180 bottom
CA15  0.1U_0402_16V7K  [C_0402]  28.74 35.46 180 bottom
CA16  0.1U_0402_16V7K  [C_0402]  29.42 24.93 270 top
CA17  10U_0603_6.3V6M  [C_0603]  28.34 24.92 270 top
CA18  10P_0402_50V8J  [C_0402]  37.14 24.48 0 bottom
CA19  0.1U_0402_16V7K  [C_0402]  33.36 21.3 180 top
CA20  2.2U_0402_6.3V6M  [C_0402]  30.76 24.86 180 bottom
CA21  2.2U_0402_6.3V6M  [C_0402]  30.06 23.72 180 bottom
CA23  0.1U_0402_16V7K  [C_0402]  33.98 25 270 top
CA24  2.2U_0402_6.3V6M  [C_0402]  28.58 29.32 270 top
CA25  2.2U_0402_6.3V6M  [C_0402]  28.48 26.65 90 top
CA26  0.1U_0402_16V7K  [C_0402]  27.34 34.51 180 bottom
CA27  2.2U_0402_6.3V6M  [C_0402]  27.34 33.62 180 bottom
CA28  0.1U_0402_16V7K  [C_0402]  32.55 24.86 180 bottom
CA29  10U_0603_6.3V6M  [C_0603]  32.71 23.72 180 bottom
CA30  0.1U_0402_16V7K  [C_0402]  31.2 24.93 270 top
CA31  4.7U_0603_6.3V6M  [C_0603]  32.28 24.86 270 top
CA32  10U_0603_6.3V6M  [C_0603]  28.98 35.4 180 top
CA33  10U_0603_6.3V6M  [C_0603]  27.02 32.57 180 bottom
CA34  10P_0402_50V8J  [C_0402]  36.76 37.05 0 bottom
CA35  22P_0402_50V8J  [C_0402]  36.76 35.72 0 bottom
CA36  22P_0402_50V8J  [C_0402]  39.06 32.6 0 bottom
CA37  22P_0402_50V8J  [C_0402]  38.17 34.53 270 bottom
CA38  22P_0402_50V8J  [C_0402]  36.19 37.03 90 top
CA39  22P_0402_50V8J  [C_0402]  38.17 35.34 270 top
CA40  22P_0402_50V8J  [C_0402]  37.42 32.59 90 top
CA41  0.1U_0402_10V7K  [C_0402]  37.47 29.68 0 bottom
CA42  100P_0201_50V8J  [C_0201]  23.67 19.65 180 bottom
CA43  100P_0201_50V8J  [C_0201]  19.02 15.71 180 bottom
CA44  0.01U_0201_16V7  [C_0201]  18.09 23.45 270 top
CA45  680P_0402_50V8J  [C_0402]  27.82 19.48 270 bottom
CA46  680P_0402_50V8J  [C_0402]  28.71 17.74 90 bottom
CA47  330U_D2E_6.3VM_R25M  [C_D2E]  25.41 27.85 270 bottom
CA48  100P_0201_50V8J  [C_0201]  21.18 22.56 270 top
CA49  330U_D2E_6.3VM_R25M  [C_D2E]  20.65 27.85 270 bottom
CA50  100P_0201_50V8J  [C_0201]  21.12 24.12 180 top
CA51  0.01U_0201_16V7  [C_0201]  22.04 26.22 90 top
CA52  10U_0603_25V6M  [C_0603]  38.24 6.76 180 bottom
CA53  0.1U_0402_25V7K  [C_0402]  38.93 7.03 270 top
CA54  1000P_0402_50V7K  [C_0402]  38.16 4.97 0 top
CA55  10U_0603_25V6M  [C_0603]  29.16 4.86 180 top
CA56  0.1U_0402_25V7K  [C_0402]  30.87 6.18 90 bottom
CA57  1000P_0402_50V7K  [C_0402]  29.23 5.94 180 top
CA58  10U_0402_6.3V6M  [C_0402]  36.9 15.39 90 top
CA59  0.1U_0402_16V7K  [C_0402]  36.01 15.39 90 top
CA60  0.1U_0402_16V7K  [C_0402]  35.12 15.39 90 top
CA61  10U_0603_25V6M  [C_0603]  28.39 10.13 0 bottom
CA62  0.1U_0402_25V7K  [C_0402]  27.75 10.34 270 top
CA63  1000P_0402_50V7K  [C_0402]  28.64 10.34 270 top
CA64  10U_0402_6.3V6M  [C_0402]  36.51 14.96 0 bottom
CA65  0.1U_0402_16V7K  [C_0402]  36.51 15.85 0 bottom
CA66  1U_0402_16V6K  [C_0402]  27.87 8.1 0 top
CA67  .033U_0603_50V7  [C_0603]  39.52 6.01 45 bottom
CA68  .033U_0603_50V7  [C_0603]  36.13 4.04 180 top
CA69  .033U_0603_50V7  [C_0603]  32.39 4.14 0 top
CA70  .033U_0603_50V7  [C_0603]  27.69 7.02 0 top
CA71  1U_0402_16V6K  [C_0402]  38.37 8.74 180 bottom
CA74  0.1U_0402_16V7K  [C_0402]  33.85 15.01 90 bottom
CA77  10U_0402_6.3V6M  [C_0402]  35.25 13.51 270 bottom
CA78  0.1U_0402_16V7K  [C_0402]  34.37 13.51 270 bottom
CA79  10U_0603_25V6M  [C_0603]  33.73 5.62 90 bottom
CA80  0.1U_0402_25V7K  [C_0402]  34.81 5.92 90 bottom
CA81  1000P_0402_50V7K  [C_0402]  35.7 5.92 90 bottom
CA82  10U_0603_25V6M  [C_0603]  29.79 6.19 90 bottom
CA83  0.1U_0402_25V7K  [C_0402]  31.76 5.73 90 bottom
CA84  1000P_0402_50V7K  [C_0402]  32.65 5.73 90 bottom
CA85  10U_0402_6.3V6M  [C_0402]  34.93 24.99 270 top
CA87  330P_0402_50V7  [C_0402]  38.22 4.67 0 bottom
CA88  330P_0402_50V7  [C_0402]  36.19 2.99 180 top
CA89  330P_0402_50V7  [C_0402]  33.52 2.95 0 top
CA90  330P_0402_50V7  [C_0402]  31 3.35 270 top
CA91  680P_0402_50V8J  [C_0402]  18.26 16.68 270 top
CA92  680P_0402_50V8J  [C_0402]  18.42 19.2 90 top
CA254  1000P_0402_50V7K  [C_0402]  38.24 3.22 90 top
CA255  1000P_0402_50V7K  [C_0402]  35.84 4.22 180 bottom
CA256  1000P_0402_50V7K  [C_0402]  32.95 1.45 0 top
CA257  1000P_0402_50V7K  [C_0402]  29.98 3.35 270 top
CC1  0.22U_0201_6.3V  [C_0201]  200.35 95.3 0 bottom
CC2  0.22U_0201_6.3V  [C_0201]  198 96.74 0 bottom
CC3  0.22U_0201_6.3V  [C_0201]  200.35 98.07 0 bottom
CC4  0.22U_0201_6.3V  [C_0201]  198.37 99.83 0 bottom
CC5  0.22U_0201_6.3V  [C_0201]  200.35 100.88 0 bottom
CC6  0.22U_0201_6.3V  [C_0201]  198.51 102.34 0 bottom
CC7  0.22U_0201_6.3V  [C_0201]  200.35 103.66 0 bottom
CC8  0.22U_0201_6.3V  [C_0201]  198 104.93 0 bottom
CC9  0.22U_0201_6.3V  [C_0201]  153.93 171.86 90 bottom
CC10  0.22U_0201_6.3V  [C_0201]  155.14 173.77 90 bottom
CC11  0.22U_0201_6.3V  [C_0201]  156.03 171.89 90 bottom
CC12  0.22U_0201_6.3V  [C_0201]  157.78 173.76 90 bottom
CC13  0.22U_0201_6.3V  [C_0201]  200.35 94.38 0 bottom
CC14  0.22U_0201_6.3V  [C_0201]  198 95.81 0 bottom
CC15  0.22U_0201_6.3V  [C_0201]  200.35 97.15 0 bottom
CC16  0.22U_0201_6.3V  [C_0201]  198.37 98.9 0 bottom
CC17  0.22U_0201_6.3V  [C_0201]  200.35 99.96 0 bottom
CC18  0.22U_0201_6.3V  [C_0201]  198.51 101.36 0 bottom
CC19  0.22U_0201_6.3V  [C_0201]  200.35 102.73 0 bottom
CC20  0.22U_0201_6.3V  [C_0201]  198 104 0 bottom
CC21  0.22U_0201_6.3V  [C_0201]  153.04 171.86 90 bottom
CC22  0.22U_0201_6.3V  [C_0201]  154.25 173.77 90 bottom
CC23  0.22U_0201_6.3V  [C_0201]  155.45 171.87 90 bottom
CC24  0.22U_0201_6.3V  [C_0201]  156.86 173.76 90 bottom
CD1  1U_0402_6.3V6K~D  [C_0402]  173.12 60.39 270 top
CD2  1U_0402_6.3V6K~D  [C_0402]  164.66 60.43 270 top
CD3  1U_0402_6.3V6K~D  [C_0402]  179.27 60.63 0 top
CD4  1U_0402_6.3V6K~D  [C_0402]  179.27 59.74 0 top
CD5  10U_0603_6.3V6M~D  [C_0603]  150.01 60.57 270 top
CD6  10U_0603_6.3V6M~D  [C_0603]  143.91 60.57 270 top
CD7  10U_0603_6.3V6M~D  [C_0603]  139.91 60.57 270 top
CD8  10U_0603_6.3V6M~D  [C_0603]  139.47 51.23 90 top
CD9  10U_0603_6.3V6M~D  [C_0603]  179.03 61.71 0 top
CD10  10U_0603_6.3V6M~D  [C_0603]  179.03 62.92 0 top
CD11  220U_D7_2VM_R6M  [C_EEFSS0D221R]  163 74.07 0 top
CD12  1U_0402_6.3V6K~D  [C_0402]  178.4 49.07 180 top
CD13  10U_0603_6.3V6M~D  [C_0603]  179.46 50.77 0 top
CD14  10U_0603_6.3V6M~D  [C_0603]  178.84 47.99 180 top
CD15  10U_0603_6.3V6M~D  [C_0603]  179.46 52.04 0 top
CD16  0.1U_0402_16V7K~D  [C_0402]  176.63 62.85 180 top
CD17  2.2U_0603_6.3V6K~D  [C_0603]  176.87 63.93 180 top
CD18  0.1U_0402_16V7K~D  [C_0402]  154.45 51.35 90 top
CD19  1U_0402_6.3V6K~D  [C_0402]  130.19 47.69 270 top
CD20  1U_0402_6.3V6K~D  [C_0402]  163.21 47.69 270 top
CD21  1U_0402_6.3V6K~D  [C_0402]  134.62 40.88 90 top
CD22  1U_0402_6.3V6K~D  [C_0402]  114.44 39.41 270 top
CD23  10U_0603_6.3V6M~D  [C_0603]  140.48 38.47 90 top
CD24  10U_0603_6.3V6M~D  [C_0603]  149.73 47.8 270 top
CD25  10U_0603_6.3V6M~D  [C_0603]  153.82 47.74 270 top
CD26  10U_0603_6.3V6M~D  [C_0603]  143.21 38.47 90 top
CD27  10U_0603_6.3V6M~D  [C_0603]  180.3 48.18 0 top
CD28  10U_0603_6.3V6M~D  [C_0603]  180.3 49.39 0 top
CD29  0.1U_0402_16V7K~D  [C_0402]  154.44 39.42 0 top
CD30  1U_0402_6.3V6K~D  [C_0402]  180.54 47.1 0 top
CD31  1U_0402_6.3V6K~D  [C_0402]  180.54 46.21 0 top
CD32  1U_0402_6.3V6K~D  [C_0402]  179.67 39.99 180 top
CD33  220U_D7_2VM_R6M  [C_EEFSS0D221R]  159.11 74.07 180 top
CD34  0.1U_0402_16V7K~D  [C_0402]  177.57 45.75 180 top
CD35  2.2U_0603_6.3V6K~D  [C_0603]  178.26 46.79 180 top
CD69  0.1U_0402_16V7K~D  [C_0402]  137.43 52.26 270 top
CD70  10U_0603_6.3V6M~D  [C_0603]  153.44 60.57 270 top
CD71  10U_0603_6.3V6M~D  [C_0603]  150.31 51.21 90 top
CD72  10U_0603_6.3V6M~D  [C_0603]  151.91 51.23 90 top
CD73  10U_0603_6.3V6M~D  [C_0603]  140.72 51.21 90 top
CD74  1U_0402_6.3V6K~D  [C_0402]  168.49 52.32 270 top
CD75  1U_0402_6.3V6K~D  [C_0402]  124.92 51.35 90 top
CD76  1U_0402_6.3V6K~D  [C_0402]  135.47 51.35 90 top
CD77  1U_0402_6.3V6K~D  [C_0402]  157.94 52.32 270 top
CD78  1U_0402_6.3V6K~D  [C_0402]  130.13 60.51 270 top
CD79  1U_0402_6.3V6K~D  [C_0402]  119.53 60.45 270 top
CD80  1U_0402_6.3V6K~D  [C_0402]  158.01 39.5 270 top
CD81  1U_0402_6.3V6K~D  [C_0402]  168.42 38.52 90 top
CD82  1U_0402_6.3V6K~D  [C_0402]  171.97 45.07 270 top
CD83  1U_0402_6.3V6K~D  [C_0402]  120.2 49.31 0 top
CD84  10U_0603_6.3V6M~D  [C_0603]  140.66 47.78 270 top
CD85  10U_0603_6.3V6M~D  [C_0603]  146.38 45.05 0 top
CD86  10U_0603_6.3V6M~D  [C_0603]  151.59 38.47 90 top
CD87  10U_0603_6.3V6M~D  [C_0603]  139.26 47.78 270 top
CD88  10U_0603_6.3V6M~D  [C_0603]  179.98 38.91 180 top
CD89  10U_0603_6.3V6M~D  [C_0603]  179.98 36.37 180 top
CD90  10U_0603_6.3V6M~D  [C_0603]  179.98 37.58 180 top
CD91  0.1U_0402_16V7K~D  [C_0402]  138.34 50.4 270 top
CD92  0.1U_0402_16V7K~D  [C_0402]  138.44 39.48 270 top
CE1  1U_0402_6.3V  [C_0402]  318.69 7.07 270 top
CE3  0.1U_0402_16V4Z~D  [C_0402]  316.79 7.07 270 top
CE4  22P_0402_50V8J~D  [C_0402]  317.74 6.15 90 top
CE6  1U_0402_6.3V  [C_0402]  322.63 7.07 270 top
CE7  0.1U_0402_16V4Z~D  [C_0402]  321.74 7.07 270 top
CE9  0.1U_0402_16V4Z~D  [C_0402]  318.07 19.64 90 top
CE13  0.1U_0402_16V4Z~D  [C_0402]  322.75 16.48 0 top
CE14  0.1U_0402_16V4Z~D  [C_0402]  322.74 15.56 0 top
CE15  0.1U_0402_16V4Z~D  [C_0402]  322.74 14.67 0 top
CE16  0.1U_0402_16V4Z~D  [C_0402]  322.74 13.81 0 top
CE17  0.1U_0402_16V4Z~D  [C_0402]  322.75 12.92 0 top
CE18  0.1U_0402_16V4Z~D  [C_0402]  322.75 12.03 0 top
CE19  0.1U_0402_16V4Z~D  [C_0402]  99.12 20.1 0 bottom
CE20  22P_0402_50V8J~D  [C_0402]  94.89 12.96 270 bottom
CE22  4.7U_0603_10V  [C_0603]  102.69 24.1 0 bottom
CE24  0.1U_0402_16V4Z  [C_0402]  223.57 154.72 0 top
CE25  0.1U_0402_16V4Z  [C_0402]  188.74 24.06 90 top
CE27  0.1U_0402_16V7K  [C_0402]  309.11 15.82 0 top
CE28  0.1U_0402_10V7K  [C_0402]  290.01 7.53 180 top
CE29  0.1U_0402_10V7K  [C_0402]  297.05 25.91 90 top
CE30  0.1U_0402_10V7K  [C_0402]  303.02 25.91 90 top
CE31  1000P_0402_50V7K  [C_0402]  287.7 24.48 0 top
CE32  1000P_0402_50V7K  [C_0402]  309.17 23.05 270 top
CE33  0.1U_0402_10V7K  [C_0402]  287.45 11.08 0 top
CE34  0.047U_0402_16V4Z  [C_0402]  301.24 25.91 90 top
CE35  100P_0402_50V8J  [C_0402]  288.98 10 0 top
CE36  0.1U_0402_10V7K  [C_0402]  302.21 27.76 180 top
CE38  0.1U_0402_10V7K  [C_0402]  309.11 19.51 0 top
CE40  100P_0402_50V8J  [C_0402]  310.02 13.79 180 top
CE41  0.1U_0402_10V7K  [C_0402]  303.91 25.91 90 top
CE42  0.1U_0402_10V7K  [C_0402]  304.99 6.08 270 top
CE43  0.1U_0402_10V7K  [C_0402]  309.11 17.73 0 top
CE44  0.1U_0402_10V7K  [C_0402]  293.11 25.48 90 top
CE45  0.1U_0402_10V7K  [C_0402]  300.36 25.91 90 top
CE46  0.1U_0402_10V7K  [C_0402]  296.05 6.65 270 top
CE51  0.033U_0402_25V  [C_0402]  310.02 9.05 180 top
CE55  0.1U_0402_16V7K~D  [C_0402]  331.42 38.31 90 top
CE56  0.1U_0402_16V4Z  [C_0402]  327.68 42.07 180 top
CE57  10P_0402_50V8J  [C_0402]  314.74 7.56 0 top
CE58  10P_0402_50V8J  [C_0402]  313.34 19.72 90 top
CE59  10P_0402_50V8J  [C_0402]  319.64 7.07 270 top
CE60  10P_0402_50V8J  [C_0402]  320.85 7.07 270 top
CE61  0.1U_0402_16V4Z  [C_0402]  220.25 166.12 270 bottom
CE62  0.1U_0402_16V4Z  [C_0402]  304.87 49.49 90 top
CE63  0.1U_0402_16V7K~D  [C_0402]  307.79 46.37 90 top
CE64  0.1U_0402_16V7K  [C_0402]  101.34 20.66 90 top
CE65  10U_0402_6.3V6M  [C_0402]  101.94 20.17 0 bottom
CE79  0.1U_0402_10V6K  [C_0402]  145.39 166.67 0 top
CE80  4.7U_0805_10V4Z  [C_0805]  144.5 165.35 180 top
CE81  0.1U_0402_10V6K  [C_0402]  153.36 163.21 90 top
CE82  0.1U_0402_10V6K  [C_0402]  143.6 163.24 180 top
CE84  0.1U_0402_16V4Z  [C_0402]  44.38 47.4 0 bottom
CE85  0.1U_0402_16V4Z  [C_0402]  33.36 48.8 180 bottom
CE86  0.1U_0402_16V4Z  [C_0402]  284.54 31.15 0 bottom
CE87  0.1U_0402_16V4Z  [C_0402]  275.4 32.8 0 bottom
CE168  0.1U_0402_16V4Z  [C_0402]  286.77 42.58 180 bottom
CF4  22U_0603_6.3V6M  [C_0603]  107.77 60.95 270 top
CF5  22U_0805_6.3VAM  [C_0805]  290.22 74.11 180 top
CG1  0.22U_0201_6.3V  [C_0201]  201.34 95.92 180 top
CG2  0.22U_0201_6.3V  [C_0201]  201.34 96.55 180 top
CG3  0.22U_0201_6.3V  [C_0201]  202.99 96.93 180 top
CG4  0.22U_0201_6.3V  [C_0201]  202.99 97.57 180 top
CG5  0.22U_0201_6.3V  [C_0201]  201.34 97.95 180 top
CG6  0.22U_0201_6.3V  [C_0201]  201.41 98.58 180 top
CG7  0.22U_0201_6.3V  [C_0201]  202.99 99.09 180 top
CG8  0.22U_0201_6.3V  [C_0201]  202.99 99.73 180 top
CG9  0.22U_0201_6.3V  [C_0201]  201.34 102.33 180 top
CG10  0.22U_0201_6.3V  [C_0201]  201.34 101.7 180 top
CG11  0.22U_0201_6.3V  [C_0201]  202.99 102.9 180 top
CG12  0.22U_0201_6.3V  [C_0201]  202.99 103.54 180 top
CG13  0.22U_0201_6.3V  [C_0201]  201.34 104.49 180 top
CG14  0.22U_0201_6.3V  [C_0201]  201.34 105.19 180 top
CG15  0.22U_0201_6.3V  [C_0201]  202.99 105.82 180 top
CG16  0.22U_0201_6.3V  [C_0201]  202.99 106.46 180 top
CG17  10U_0603_6.3V6M  [C_0603]  230.62 88.57 90 top
CG18  1U_0201_6.3V6K  [C_0201]  230.3 87.63 270 top
CG19  1U_0201_6.3V6K  [C_0201]  231.53 88.45 90 top
CG20  1U_0201_6.3V6K  [C_0201]  232.61 88.45 90 top
CG21  1U_0201_6.3V6K  [C_0201]  224.2 94.33 180 top
CG22  1U_0201_6.3V6K  [C_0201]  224.2 96.81 180 top
CG23  1U_0201_6.3V6K  [C_0201]  224.14 99.22 180 top
CG24  1U_0201_6.3V6K  [C_0201]  224.14 89.63 180 top
CG25  1U_0201_6.3V6K  [C_0201]  224.2 95.54 180 top
CG26  1U_0201_6.3V6K  [C_0201]  227.33 92 180 top
CG27  1U_0201_6.3V6K  [C_0201]  224.07 91.98 180 top
CG28  1U_0201_6.3V6K  [C_0201]  223.63 93.19 180 top
CG29  10U_0603_6.3V6M  [C_0603]  225.92 99.49 0 top
CG30  10U_0603_6.3V6M  [C_0603]  225.16 87.05 0 top
CG31  1U_0201_6.3V6K  [C_0201]  214.26 82.04 90 bottom
CG32  10U_0603_6.3V6M  [C_0603]  233.69 86.51 270 top
CG33  1U_0402_6.3V4Z  [C_0402]  233.82 88.87 270 top
CG34  0.1U_0201_6.3V6K  [C_0201]  214.26 80.77 90 bottom
CG35  10U_0603_6.3V6M  [C_0603]  231.21 87.6 270 top
CG41  0.1U_0402_25V6K~D  [C_0402]  212.4 115.51 270 bottom
CG42  1U_0402_6.3V4Z  [C_0402]  231.05 80.57 0 top
CG43  0.1U_0402_10V6K  [C_0402]  231.05 81.46 0 top
CG44  1U_0201_6.3V6K  [C_0201]  245.61 107.65 180 top
CG45  1U_0201_6.3V6K  [C_0201]  243.05 100.59 0 top
CG46  1U_0201_6.3V6K  [C_0201]  229.75 104.05 180 top
CG47  1U_0201_6.3V6K  [C_0201]  238.54 101.6 0 top
CG48  1U_0201_6.3V6K  [C_0201]  238.54 102.6 0 top
CG49  1U_0201_6.3V6K  [C_0201]  240.23 91.51 270 top
CG50  22U_0402_6.3V6K  [C_0402]  233.82 90.66 270 top
CG51  22U_0402_6.3V6K  [C_0402]  229.04 90.8 180 top
CG52  1U_0201_6.3V6K  [C_0201]  248.23 92.04 0 top
CG53  1U_0201_6.3V6K  [C_0201]  246.13 95.66 180 top
CG54  1U_0201_6.3V6K  [C_0201]  246.83 108.74 0 top
CG55  1U_0201_6.3V6K  [C_0201]  229.03 107.31 270 top
CG56  1U_0201_6.3V6K  [C_0201]  229.75 104.68 180 top
CG57  1U_0201_6.3V6K  [C_0201]  235.01 107.24 270 top
CG58  1U_0201_6.3V6K  [C_0201]  227.95 102.78 180 top
CG59  1U_0201_6.3V6K  [C_0201]  227.44 105.2 0 top
CG60  1U_0201_6.3V6K  [C_0201]  245.42 102.8 0 top
CG61  1U_0201_6.3V6K  [C_0201]  226.16 106.32 0 top
CG62  1U_0201_6.3V6K  [C_0201]  248.62 104 0 top
CG63  1U_0201_6.3V6K  [C_0201]  247.02 105.2 0 top
CG64  1U_0201_6.3V6K  [C_0201]  243.66 94.61 180 top
CG65  1U_0201_6.3V6K  [C_0201]  245.31 96.81 0 top
CG66  1U_0201_6.3V6K  [C_0201]  240 92.6 0 top
CG67  1U_0201_6.3V6K  [C_0201]  238.03 92.62 0 top
CG68  1U_0201_6.3V6K  [C_0201]  237.6 91.54 180 top
CG69  1U_0201_6.3V6K  [C_0201]  244.65 89.59 0 top
CG70  1U_0201_6.3V6K  [C_0201]  242.52 99.6 0 top
CG71  1U_0201_6.3V6K  [C_0201]  230.83 92.34 270 top
CG72  1U_0201_6.3V6K  [C_0201]  229.82 92.34 270 top
CG73  1U_0201_6.3V6K  [C_0201]  231.84 92.34 270 top
CG74  1U_0201_6.3V6K  [C_0201]  232.65 93.61 180 top
CG75  1U_0201_6.3V6K  [C_0201]  234.48 93.6 0 top
CG76  22U_0402_6.3V6K  [C_0402]  244.42 97.14 270 top
CG77  22U_0402_6.3V6K  [C_0402]  235.2 90.04 0 top
CG78  22U_0402_6.3V6K  [C_0402]  229.11 92 180 top
CG79  22U_0805_6.3VAM  [C_0805]  229.6 101.46 90 top
CG80  22U_0805_6.3VAM  [C_0805]  244.15 98.73 0 top
CG81  22U_0805_6.3VAM  [C_0805]  232.36 104.12 0 top
CG82  22U_0805_6.3VAM  [C_0805]  231.3 102.67 270 top
CG83  1U_0201_6.3V6K  [C_0201]  232.65 94.6 180 top
CG84  1U_0201_6.3V6K  [C_0201]  234.1 102.6 0 top
CG85  1U_0201_6.3V6K  [C_0201]  235.66 89.31 0 top
CG86  22U_0402_6.3V6K  [C_0402]  229.12 93.19 180 top
CG87  22U_0402_6.3V6K  [C_0402]  229.74 98 180 top
CG88  1U_0201_6.3V6K  [C_0201]  248.81 90.84 180 top
CG89  1U_0201_6.3V6K  [C_0201]  254.32 108.51 90 top
CG90  1U_0201_6.3V6K  [C_0201]  247.02 106.4 0 top
CG91  1U_0201_6.3V6K  [C_0201]  242.48 92.6 0 top
CG92  1U_0201_6.3V6K  [C_0201]  242.99 105.63 0 top
CG93  1U_0201_6.3V6K  [C_0201]  234.1 101.59 0 top
CG94  22U_0402_6.3V6K  [C_0402]  229.73 100.4 180 top
CG95  22U_0402_6.3V6K  [C_0402]  229.11 99.2 180 top
CG96  1U_0201_6.3V6K  [C_0201]  242.86 91.6 0 top
CG97  1U_0201_6.3V6K  [C_0201]  235.66 106.27 270 top
CG98  1U_0201_6.3V6K  [C_0201]  242.2 100.6 180 top
CG99  1U_0201_6.3V6K  [C_0201]  227.78 106.51 90 top
CG100  1U_0201_6.3V6K  [C_0201]  226.62 105.2 180 top
CG101  1U_0201_6.3V6K  [C_0201]  230.22 108.1 270 top
CG102  1U_0201_6.3V6K  [C_0201]  245.48 105.19 180 top
CG103  1U_0201_6.3V6K  [C_0201]  240.65 101.59 180 top
CG104  1U_0201_6.3V6K  [C_0201]  236.06 92.59 0 top
CG105  1U_0201_6.3V6K  [C_0201]  242.41 93.6 0 top
CG106  22U_0402_6.3V6K  [C_0402]  228.16 94.4 180 top
CG107  22U_0402_6.3V6K  [C_0402]  228.21 96.8 180 top
CG108  22U_0402_6.3V6K  [C_0402]  241.02 91.44 270 top
CG109  10U_0805_6.3V7K  [C_0805]  236.97 105.91 90 top
CG110  22U_0402_6.3V6K  [C_0402]  236.77 104.55 180 top
CG111  22U_0402_6.3V6K  [C_0402]  235.09 88.63 270 top
CG112  22U_0402_6.3V6K  [C_0402]  238.62 90.92 270 top
CG113  22U_0402_6.3V6K  [C_0402]  237.41 90.81 270 top
CG114  1U_0201_6.3V6K  [C_0201]  239.66 91.51 270 top
CG115  1U_0201_6.3V6K  [C_0201]  238.22 91.6 0 top
CG116  1U_0201_6.3V6K  [C_0201]  240.65 102.61 180 top
CG117  1U_0201_6.3V6K  [C_0201]  233.22 101.6 180 top
CG118  1U_0201_6.3V6K  [C_0201]  233.22 102.6 180 top
CG119  1U_0201_6.3V6K  [C_0201]  236.23 88.07 90 top
CG120  1U_0201_6.3V6K  [C_0201]  241.56 94.6 180 top
CG121  1U_0201_6.3V6K  [C_0201]  236.03 103.58 0 top
CG122  1U_0201_6.3V6K  [C_0201]  240.99 89.35 270 top
CG123  1U_0201_6.3V6K  [C_0201]  234.54 94.6 0 top
CG124  10U_0603_6.3V6M  [C_0603]  204.01 81.27 180 bottom
CG125  0.1U_0402_10V7K  [C_0402]  204.01 82.48 180 bottom
CG126  47U_0805_6.3V6M~D  [C_0805]  268.23 86.99 270 top
CG127  47U_0805_6.3V6M~D  [C_0805]  259.45 86.6 0 bottom
CG128  47U_0805_6.3V6M~D  [C_0805]  259.45 84.76 0 bottom
CG129  47U_0805_6.3V6M~D  [C_0805]  223.63 120.51 90 bottom
CG130  0.1U_0402_10V7K  [C_0402]  208.29 87.03 180 bottom
CG131  0.1U_0402_10V7K  [C_0402]  202.55 90.54 0 bottom
CG132  1U_0402_6.3V6K  [C_0402]  238.62 107.25 270 top
CG133  120P_0402_50V9  [C_0402]  255.86 110.15 225 top
CG134  1U_0402_6.3V6K  [C_0402]  232.77 105.91 0 top
CG135  120P_0402_50V9  [C_0402]  253.99 91.8 90 top
CG136  1U_0402_6.3V6K  [C_0402]  244.4 101.59 90 top
CG137  1U_0402_6.3V6K  [C_0402]  243.97 93.84 270 top
CG138  1U_0402_6.3V6K  [C_0402]  224.55 128.07 90 bottom
CG139  1U_0402_6.3V6K  [C_0402]  207.14 128.01 0 bottom
CG140  1U_0402_6.3V6K  [C_0402]  226.34 128.97 270 bottom
CG141  1U_0402_6.3V6K  [C_0402]  208.05 128.89 180 bottom
CG142  1U_0402_6.3V6K  [C_0402]  201.8 134.86 0 bottom
CG143  1U_0402_6.3V6K  [C_0402]  230.39 140.72 270 top
CG144  1U_0402_6.3V6K  [C_0402]  202.72 137.91 180 bottom
CG145  1U_0402_6.3V6K  [C_0402]  230.39 138.94 270 top
CG146  10U_0603_6.3V6M  [C_0603]  218.66 146.39 0 bottom
CG147  1U_0402_6.3V4Z  [C_0402]  209.69 132.57 270 top
CG148  1U_0402_6.3V4Z  [C_0402]  210.47 127.12 180 bottom
CG149  1U_0402_6.3V4Z  [C_0402]  207.14 127.12 0 bottom
CG150  1U_0402_6.3V4Z  [C_0402]  215.98 143.64 270 top
CG151  0.1U_0402_10V6K  [C_0402]  218.58 142.92 270 top
CG152  0.1U_0402_10V6K  [C_0402]  223.47 140.51 270 top
CG153  0.1U_0402_10V6K  [C_0402]  222.53 146.17 180 bottom
CG154  0.1U_0402_10V6K  [C_0402]  230.39 143.55 90 top
CG155  0.1U_0402_10V6K  [C_0402]  215.98 135.07 270 top
CG156  0.1U_0402_10V6K  [C_0402]  215.91 139.55 90 top
CG157  0.1U_0402_10V6K  [C_0402]  209.37 140.59 270 top
CG158  0.1U_0402_10V6K  [C_0402]  202.7 140.42 90 bottom
CG159  1U_0402_6.3V4Z  [C_0402]  211.27 134.47 270 top
CG160  1U_0402_6.3V4Z  [C_0402]  229.72 135.51 90 top
CG161  1U_0402_6.3V4Z  [C_0402]  207.16 145.13 180 top
CG162  1U_0402_6.3V4Z  [C_0402]  218.9 129.02 0 bottom
CG163  10U_0603_6.3V6M  [C_0603]  209.75 136.11 270 top
CG164  1U_0402_6.3V4Z  [C_0402]  223.66 128.07 90 bottom
CG165  1U_0402_6.3V4Z  [C_0402]  222.46 148.3 180 top
CG166  1U_0402_6.3V4Z  [C_0402]  222.82 133.4 0 top
CG167  1U_0402_6.3V4Z  [C_0402]  226.65 133.13 180 top
CG168  0.1U_0402_10V6K  [C_0402]  202.7 143.62 270 bottom
CG169  0.1U_0402_10V6K  [C_0402]  226.64 142.92 270 top
CG170  0.1U_0402_10V6K  [C_0402]  225.12 141.01 90 top
CG171  0.1U_0402_10V6K  [C_0402]  218.58 144.95 270 top
CG172  0.1U_0402_10V6K  [C_0402]  229.82 133.26 90 top
CG173  0.1U_0402_10V6K  [C_0402]  215.97 145.46 270 top
CG174  0.1U_0402_10V6K  [C_0402]  208.61 134.22 270 top
CG175  0.1U_0402_10V6K  [C_0402]  216.82 129.08 180 bottom
CG176  1U_0402_6.3V4Z  [C_0402]  223.47 134.91 90 top
CG177  1U_0402_6.3V4Z  [C_0402]  225.24 134.77 90 top
CG178  1U_0402_6.3V4Z  [C_0402]  209.44 142.85 90 top
CG179  1U_0402_6.3V4Z  [C_0402]  211.22 142.78 90 top
CG180  1U_0402_6.3V6K  [C_0402]  256.11 128.06 90 bottom
CG181  1U_0402_6.3V6K  [C_0402]  239.03 146.12 270 top
CG182  1U_0402_6.3V6K  [C_0402]  254.33 128.97 270 bottom
CG183  1U_0402_6.3V6K  [C_0402]  236.36 145.2 90 top
CG184  1U_0402_6.3V6K  [C_0402]  260.76 135.63 180 bottom
CG185  1U_0402_6.3V6K  [C_0402]  235.41 146.12 270 top
CG186  1U_0402_6.3V6K  [C_0402]  259.84 138.29 0 bottom
CG187  1U_0402_6.3V6K  [C_0402]  232.74 138.06 90 top
CG188  10U_0603_6.3V6M  [C_0603]  237.76 143.88 270 top
CG189  1U_0402_6.3V4Z  [C_0402]  239.21 143.21 90 top
CG190  1U_0402_6.3V4Z  [C_0402]  234.92 135.69 270 top
CG191  1U_0402_6.3V4Z  [C_0402]  243.79 143.37 90 top
CG192  1U_0402_6.3V4Z  [C_0402]  239.69 134.09 270 top
CG193  0.1U_0402_10V6K  [C_0402]  239.21 142.35 270 top
CG194  0.1U_0402_10V6K  [C_0402]  243.72 134.59 270 top
CG195  0.1U_0402_10V6K  [C_0402]  232.74 139.87 90 top
CG196  0.1U_0402_10V6K  [C_0402]  251.14 146.17 0 bottom
CG197  0.1U_0402_10V6K  [C_0402]  243.79 139.5 90 top
CG198  0.1U_0402_10V6K  [C_0402]  232.68 143.61 90 top
CG199  0.1U_0402_10V6K  [C_0402]  236.72 134.12 270 top
CG200  0.1U_0402_10V6K  [C_0402]  235.03 139.55 90 top
CG201  1U_0402_6.3V4Z  [C_0402]  243.79 142.23 270 top
CG202  1U_0402_6.3V4Z  [C_0402]  236.68 142.04 270 top
CG203  1U_0402_6.3V4Z  [C_0402]  235.79 141.96 90 top
CG204  1U_0402_6.3V4Z  [C_0402]  242.34 145.02 180 top
CG205  10U_0603_6.3V6M  [C_0603]  248.76 146.33 0 bottom
CG206  1U_0402_6.3V4Z  [C_0402]  259.84 142.74 0 bottom
CG207  1U_0402_6.3V4Z  [C_0402]  259.84 141.09 0 bottom
CG208  1U_0402_6.3V4Z  [C_0402]  249.25 139.56 90 top
CG209  1U_0402_6.3V4Z  [C_0402]  257.63 128.97 270 bottom
CG210  0.1U_0402_10V6K  [C_0402]  253.32 141.2 90 top
CG211  0.1U_0402_10V6K  [C_0402]  246.82 134.59 270 top
CG212  0.1U_0402_10V6K  [C_0402]  246.71 143.56 270 top
CG213  0.1U_0402_10V6K  [C_0402]  259.84 133.09 0 bottom
CG214  0.1U_0402_10V6K  [C_0402]  259.84 129.91 0 bottom
CG215  0.1U_0402_10V6K  [C_0402]  259.84 134.1 0 bottom
CG216  0.1U_0402_10V6K  [C_0402]  259.84 143.75 0 bottom
CG217  0.1U_0402_10V6K  [C_0402]  251.59 143.63 0 top
CG218  1U_0402_6.3V4Z  [C_0402]  259.84 140.07 0 bottom
CG219  1U_0402_6.3V4Z  [C_0402]  259.84 130.93 0 bottom
